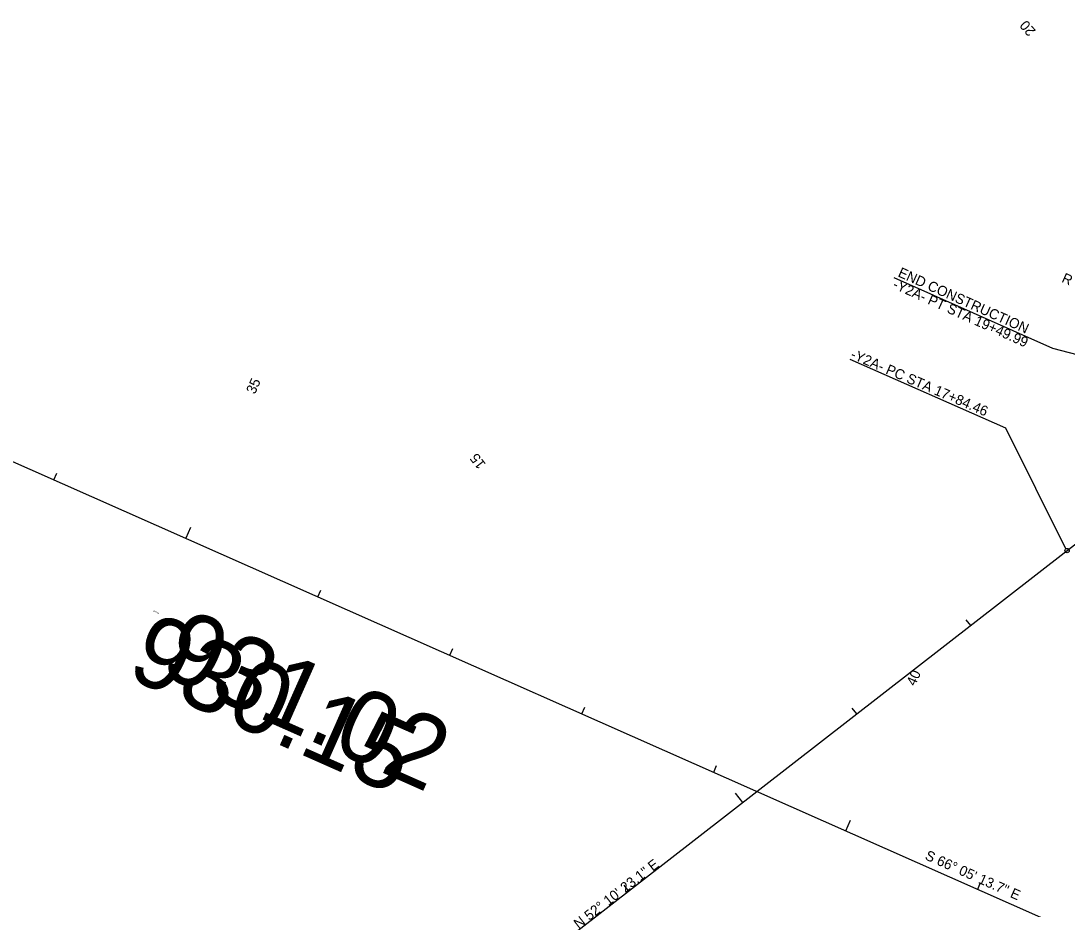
# Model space of a CAD drawing. Extents: x 1636713 to 1642783, y 841520 to 844371.
# Drawn here: x 1639007 to 1639731, y 842918 to 843533 of the extents above; entities that cross this region are included whole.
import ezdxf

# ---------------------------------------------------------------- set-up
doc = ezdxf.new("R2010")
doc.units = 0
for name, color, linetype in [('COGO Default Chain', 7, 'Continuous'), ('Default', 7, 'Continuous'), ('Prop Horizontal Alignment', 7, 'Continuous'), ('Prop Horizontal Alignment Curve and Spiral Data', 7, 'Continuous'), ('Prop Horizontal Alignment Direction Label', 7, 'Continuous'), ('Prop Horizontal Alignment Station Label', 7, 'Continuous'), ('Prop Horizontal Alignment Tick Label', 7, 'Continuous'), ('Prop Horizontal Alignment Tick Large', 7, 'Continuous'), ('Prop Horizontal Alignment Tick Small', 7, 'Continuous')]:
    doc.layers.add(name, color=color, linetype=linetype)

msp = doc.modelspace()

# ---------------------------------------------------------------- linework, layer by layer
at = {"layer": 'COGO Default Chain'}
msp.add_line((1639111.65, 842685.24), (1639731.27, 843166.33), dxfattribs=at)
msp.add_arc((1637124.83, 846523.26), 4250, 307.82692, 312.33575, dxfattribs=at)
at = {"layer": 'Prop Horizontal Alignment'}
for p, q in [((1638900.9, 843272.49), (1640357.88, 842626.45)), ((1639111.65, 842685.24), (1639731.27, 843166.33))]:
    msp.add_line(p, q, dxfattribs=at)
msp.add_arc((1637124.83, 846523.26), 4250, 307.82692, 312.33575, dxfattribs=at)
at = {"layer": 'Prop Horizontal Alignment Station Label'}
for points in [[(1639860.01, 843270.37), (1639721.5, 843306.51), (1639611.49, 843355.37)], [(1639730.35, 843167.51), (1639688.85, 843251.16), (1639581.07, 843298.86)]]:
    msp.add_lwpolyline(points, dxfattribs=at)
msp.add_circle((1639731.27, 843166.33), 1.5, dxfattribs=at)
at = {"layer": 'Prop Horizontal Alignment Tick Large'}
for p, q in [((1639124.12, 843182.26), (1639120.88, 843174.95)), ((1639506.58, 842991.88), (1639501.67, 842998.19)), ((1639577.96, 842972.28), (1639581.2, 842979.59))]:
    msp.add_line(p, q, dxfattribs=at)
at = {"layer": 'Prop Horizontal Alignment Tick Small'}
for p, q in [((1639029.46, 843215.48), (1639031.49, 843220.05)), ((1639212.29, 843134.41), (1639214.32, 843138.99)), ((1639664.55, 843114.53), (1639661.49, 843118.48)), ((1639303.71, 843093.88), (1639305.74, 843098.45)), ((1639395.13, 843053.35), (1639397.15, 843057.92)), ((1639585.57, 843053.2), (1639582.5, 843057.15)), ((1639486.54, 843012.81), (1639488.57, 843017.38)), ((1639427.59, 842930.55), (1639424.53, 842934.5)), ((1639669.37, 842931.74), (1639671.4, 842936.31))]:
    msp.add_line(p, q, dxfattribs=at)

# ---------------------------------------------------------------- texts
at = {"layer": 'Default'}
for s, height, p in [('930.15', 50, (1639078.45, 843079.28)), ('930.15', 1, (1639098.32, 843124.07)), ('931.02', 50, (1639101.48, 843081.46))]:
    msp.add_text(s, height=height, rotation=336.08714, dxfattribs=at).set_placement(p)
at = {"layer": 'Prop Horizontal Alignment Curve and Spiral Data'}
msp.add_text("R = 4,250.00'", height=7, rotation=335.96803, dxfattribs=at).set_placement((1639726.99, 843352.68))
at = {"layer": 'Prop Horizontal Alignment Direction Label'}
for s, rotation, p in [('S 66%%d 05\' 13.7" E', 336.08714, (1639632.31, 842952.59)), ('N 52%%d 10\' 23.1" E', 37.82692, (1639392.95, 842903.91))]:
    msp.add_text(s, height=7, rotation=rotation, dxfattribs=at).set_placement(p)
at = {"layer": 'Prop Horizontal Alignment Station Label'}
for s, rotation, p in [('END CONSTRUCTION', 335.85363, (1639613.58, 843356.54)), ('-Y2A- PT STA 19+49.99', 335.85363, (1639609.95, 843348.44)), ('-Y2A- PC STA 17+84.46', 336.59915, (1639580.78, 843299.85))]:
    msp.add_text(s, height=7, rotation=rotation, dxfattribs=at).set_placement(p)
at = {"layer": 'Prop Horizontal Alignment Tick Label'}
for s, rotation, p in [('20', 130.73268, (1639709.96, 843526.61)), ('35', 66.08714, (1639168.76, 843274.31)), ('15', 127.82692, (1639329, 843226.29)), ('40', 66.08714, (1639626.03, 843072.06))]:
    msp.add_text(s, height=7, rotation=rotation, dxfattribs=at).set_placement(p)

doc.saveas('drawing.dxf')
